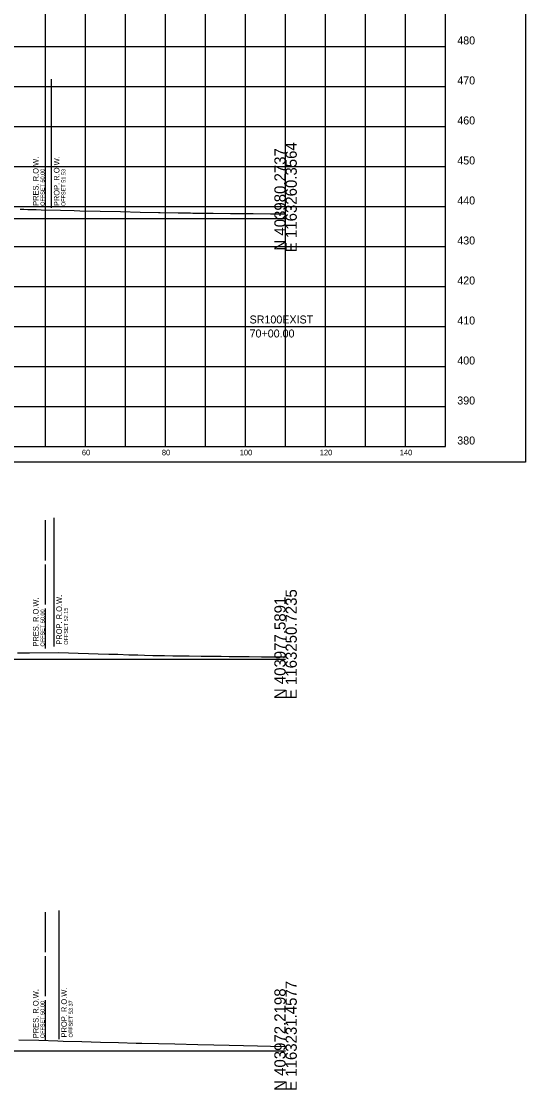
# Model space of a CAD drawing. Extents: x -314 to 907, y -5342 to 21804.
# Drawn here: x 154 to 280, y 12782.3 to 13049.3 of the extents above; entities that cross this region are included whole.
import ezdxf

# ---------------------------------------------------------------- set-up
doc = ezdxf.new("R2010")
doc.units = 0
for name, color, linetype in [('DESIGN - ROW - Right-of-Way Linework', 7, 'Continuous'), ('DESIGN - SHEET - Corner Text', 7, 'Continuous'), ('DESIGN - SHEET - Light Grid', 7, 'Continuous'), ('DESIGN - SHEET - Linework', 7, 'Continuous'), ('DESIGN - SHEET - Plot Shape', 7, 'Continuous'), ('DESIGN - TYPICAL - Warning Text', 7, 'Continuous'), ('SURVEY - GROUND - Top of Ground', 7, 'Continuous'), ('SURVEY - PROPERTY - ROW Lines', 7, 'Continuous'), ('SURVEY - PROPERTY - ROW Lines Text', 7, 'Continuous')]:
    doc.layers.add(name, color=color, linetype=linetype)

msp = doc.modelspace()

# ---------------------------------------------------------------- linework, layer by layer
at = {"layer": 'DESIGN - ROW - Right-of-Way Linework'}
for p, q in [((161.53, 13002.64), (161.53, 13034.8)), ((162.15, 12893), (162.15, 12925.16)), ((163.37, 12794.84), (163.37, 12827))]:
    msp.add_line(p, q, dxfattribs=at)
at = {"layer": 'DESIGN - SHEET - Light Grid'}
for p, q in [((110, 13000), (220, 13000)), ((110, 12889.85), (220, 12889.85)), ((110, 12791.94), (220, 12791.94))]:
    msp.add_line(p, q, dxfattribs=at)
at = {"layer": 'DESIGN - SHEET - Linework'}
for p, q in [((160, 12943), (160, 13153)), ((170, 12943), (170, 13153)), ((180, 12943), (180, 13153)), ((190, 12943), (190, 13153)), ((200, 12943), (200, 13153)), ((210, 12943), (210, 13153)), ((220, 12943), (220, 13153)), ((230, 12943), (230, 13153)), ((240, 12943), (240, 13153)), ((250, 12943), (250, 13153)), ((-40, 13043), (260, 13043)), ((-40, 13033), (260, 13033)), ((-40, 13023), (260, 13023)), ((-40, 13013), (260, 13013)), ((-40, 13003), (260, 13003)), ((-40, 12993), (260, 12993)), ((-40, 12983), (260, 12983)), ((-40, 12973), (260, 12973)), ((-40, 12963), (260, 12963)), ((-40, 12953), (260, 12953))]:
    msp.add_line(p, q, dxfattribs=at)
msp.add_lwpolyline([(-40, 13153), (-40, 12943), (260, 12943), (260, 13153)], dxfattribs=at)
at = {"layer": 'DESIGN - SHEET - Plot Shape'}
msp.add_lwpolyline([(-60, 13156.94), (280, 13156.94), (280, 12939.06), (-60, 12939.06)], close=True, dxfattribs=at)
at = {"layer": 'SURVEY - GROUND - Top of Ground'}
for points in [[(153.62, 13002.35), (154.57, 13002.31), (155.58, 13002.26), (156.5, 13002.24), (157.62, 13002.2), (158.94, 13002.16), (163.7, 13002.05), (167.16, 13001.97), (168.6, 13001.94), (173.67, 13001.83), (178.75, 13001.71), (183.66, 13001.6), (188.2, 13001.5), (188.68, 13001.49), (193.12, 13001.4), (193.71, 13001.39), (196.24, 13001.37), (196.85, 13001.36), (200.55, 13001.33), (200.94, 13001.33), (201.24, 13001.33), (201.88, 13001.32), (206.23, 13001.28), (206.9, 13001.27), (211.23, 13001.24), (211.93, 13001.23), (216.22, 13001.19), (216.95, 13001.19), (220, 13001.16)], [(152.97, 12891.47), (155.05, 12891.42), (155.97, 12891.4), (163.17, 12891.51), (165.71, 12891.41), (168.15, 12891.36), (170.76, 12891.26), (173.12, 12891.21), (175.81, 12891.11), (178.1, 12891.06), (180.85, 12890.95), (183.07, 12890.9), (184.72, 12890.83), (186.86, 12890.79), (189.74, 12890.75), (191.81, 12890.7), (194.76, 12890.67), (195.93, 12890.66), (198.92, 12890.62), (200.92, 12890.6), (203.94, 12890.57), (205.92, 12890.55), (208.97, 12890.51), (210.91, 12890.5), (214, 12890.46), (215.9, 12890.44), (219.02, 12890.4), (220, 12890.4)], [(153.32, 12794.71), (158.29, 12794.59), (163.08, 12794.46), (164.38, 12794.4), (169.11, 12794.27), (173.73, 12794.14), (178.24, 12794.02), (182.64, 12793.89), (184.04, 12793.85), (188.23, 12793.76), (192.29, 12793.67), (198.08, 12793.55), (202.09, 12793.46), (205.9, 12793.38), (209.52, 12793.3), (212.97, 12793.22), (216.26, 12793.15), (220, 12793.06)]]:
    msp.add_lwpolyline(points, dxfattribs=at)
at = {"layer": 'SURVEY - PROPERTY - ROW Lines'}
for p, q in [((160, 13024.7), (160, 13034.7)), ((160, 13013.7), (160, 13023.7)), ((160, 13002.7), (160, 13012.7)), ((160, 12914.55), (160, 12924.55)), ((160, 12903.55), (160, 12913.55)), ((160, 12892.55), (160, 12902.55)), ((160, 12816.64), (160, 12826.64)), ((160, 12805.64), (160, 12815.64)), ((160, 12794.64), (160, 12804.64))]:
    msp.add_line(p, q, dxfattribs=at)

# ---------------------------------------------------------------- texts
at = {"layer": 'DESIGN - ROW - Right-of-Way Linework'}
for s, height, p in [('PROP. R.O.W.', 1.4, (163.48, 13003.09)), ('OFFSET 51.53', 1, (164.98, 13003.09)), ('PROP. R.O.W.', 1.4, (164.1, 12893.45)), ('OFFSET 52.15', 1, (165.6, 12893.45)), ('PROP. R.O.W.', 1.4, (165.32, 12795.29)), ('OFFSET 53.37', 1, (166.82, 12795.29))]:
    msp.add_text(s, height=height, rotation=90, dxfattribs=at).set_placement(p)
at = {"layer": 'DESIGN - SHEET - Corner Text'}
for s, height, p in [('480', 2, (262.91, 13043.5)), ('470', 2, (262.91, 13033.5)), ('460', 2, (262.91, 13023.5)), ('450', 2, (262.91, 13013.5)), ('440', 2, (262.91, 13003.5)), ('430', 2, (262.91, 12993.5)), ('420', 2, (262.91, 12983.5)), ('410', 2, (262.91, 12973.5)), ('400', 2, (262.91, 12963.5)), ('390', 2, (262.91, 12953.5)), ('380', 2, (262.91, 12943.5)), ('60', 1.4, (169.08, 12940.8)), ('80', 1.4, (189.08, 12940.8)), ('100', 1.4, (208.54, 12940.8)), ('120', 1.4, (228.54, 12940.8)), ('140', 1.4, (248.54, 12940.8))]:
    msp.add_text(s, height=height, dxfattribs=at).set_placement(p)
at = {"layer": 'DESIGN - SHEET - Light Grid'}
for s, p in [('N 403980.2737', (220, 12991.97)), ('E 1163260.3564', (222.8, 12991.57)), ('N 403977.5891', (220, 12879.85)), ('E 1163250.7235', (222.8, 12879.85)), ('E 1163231.4577', (222.8, 12781.94)), ('N 403972.2198', (220, 12781.94))]:
    msp.add_text(s, height=2.8, rotation=90, dxfattribs=at).set_placement(p)
at = {"layer": 'DESIGN - TYPICAL - Warning Text'}
for s, p in [('SR100EXIST', (211, 12973.75)), ('70+00.00', (211, 12970.25))]:
    msp.add_text(s, height=2, dxfattribs=at).set_placement(p)
at = {"layer": 'SURVEY - PROPERTY - ROW Lines Text'}
for s, height, p in [('PRES. R.O.W.', 1.4, (158.25, 13003.15)), ('OFFSET 50.00', 1, (159.75, 13003.15)), ('PRES. R.O.W.', 1.4, (158.25, 12893)), ('OFFSET 50.00', 1, (159.75, 12893)), ('PRES. R.O.W.', 1.4, (158.25, 12795.1)), ('OFFSET 50.00', 1, (159.75, 12795.1))]:
    msp.add_text(s, height=height, rotation=90, dxfattribs=at).set_placement(p)

doc.saveas('drawing.dxf')
